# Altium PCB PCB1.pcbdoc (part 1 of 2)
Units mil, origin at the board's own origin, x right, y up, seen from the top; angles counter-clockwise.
Board outline 3879.65 x 2893.58 mil, 4 copper layers (Top Layer, Inner1, Inner2, Bottom Layer); 142 components, 140 nets, 675 pads, 157 vias.
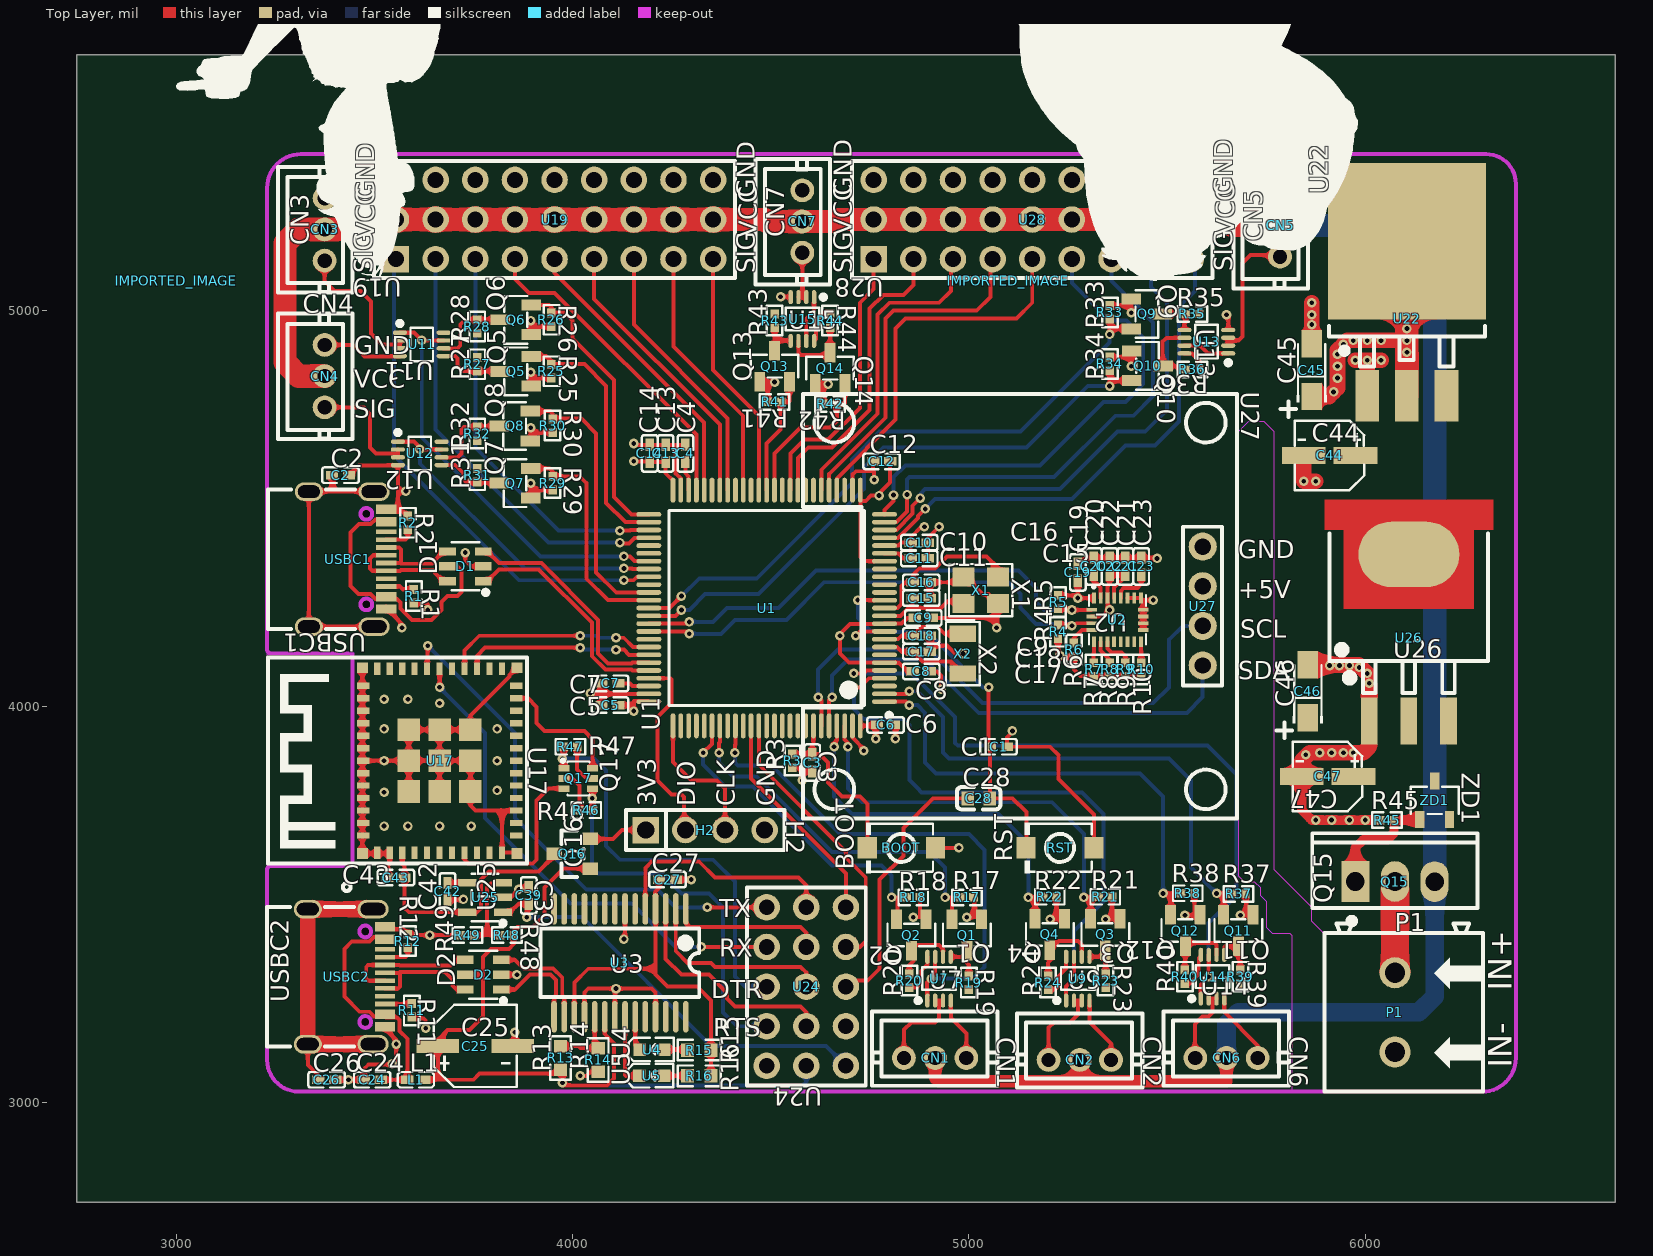
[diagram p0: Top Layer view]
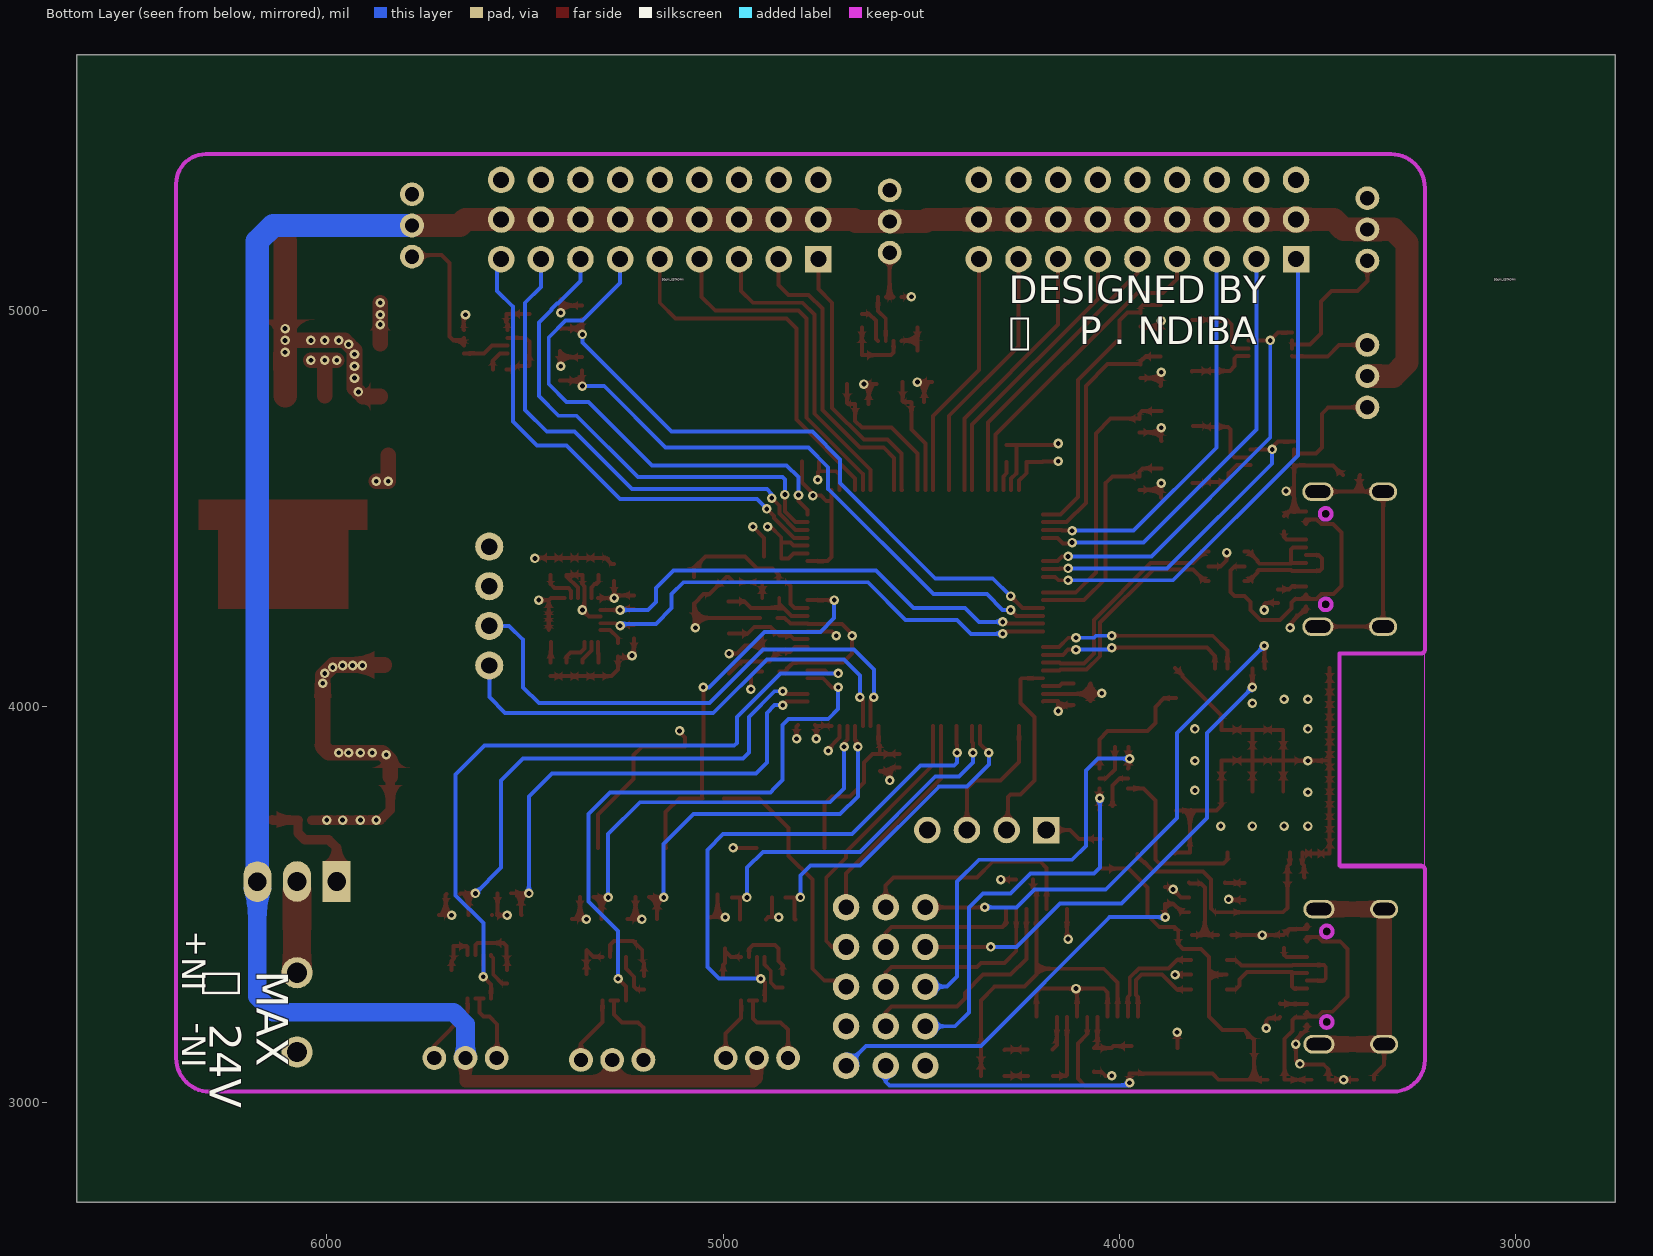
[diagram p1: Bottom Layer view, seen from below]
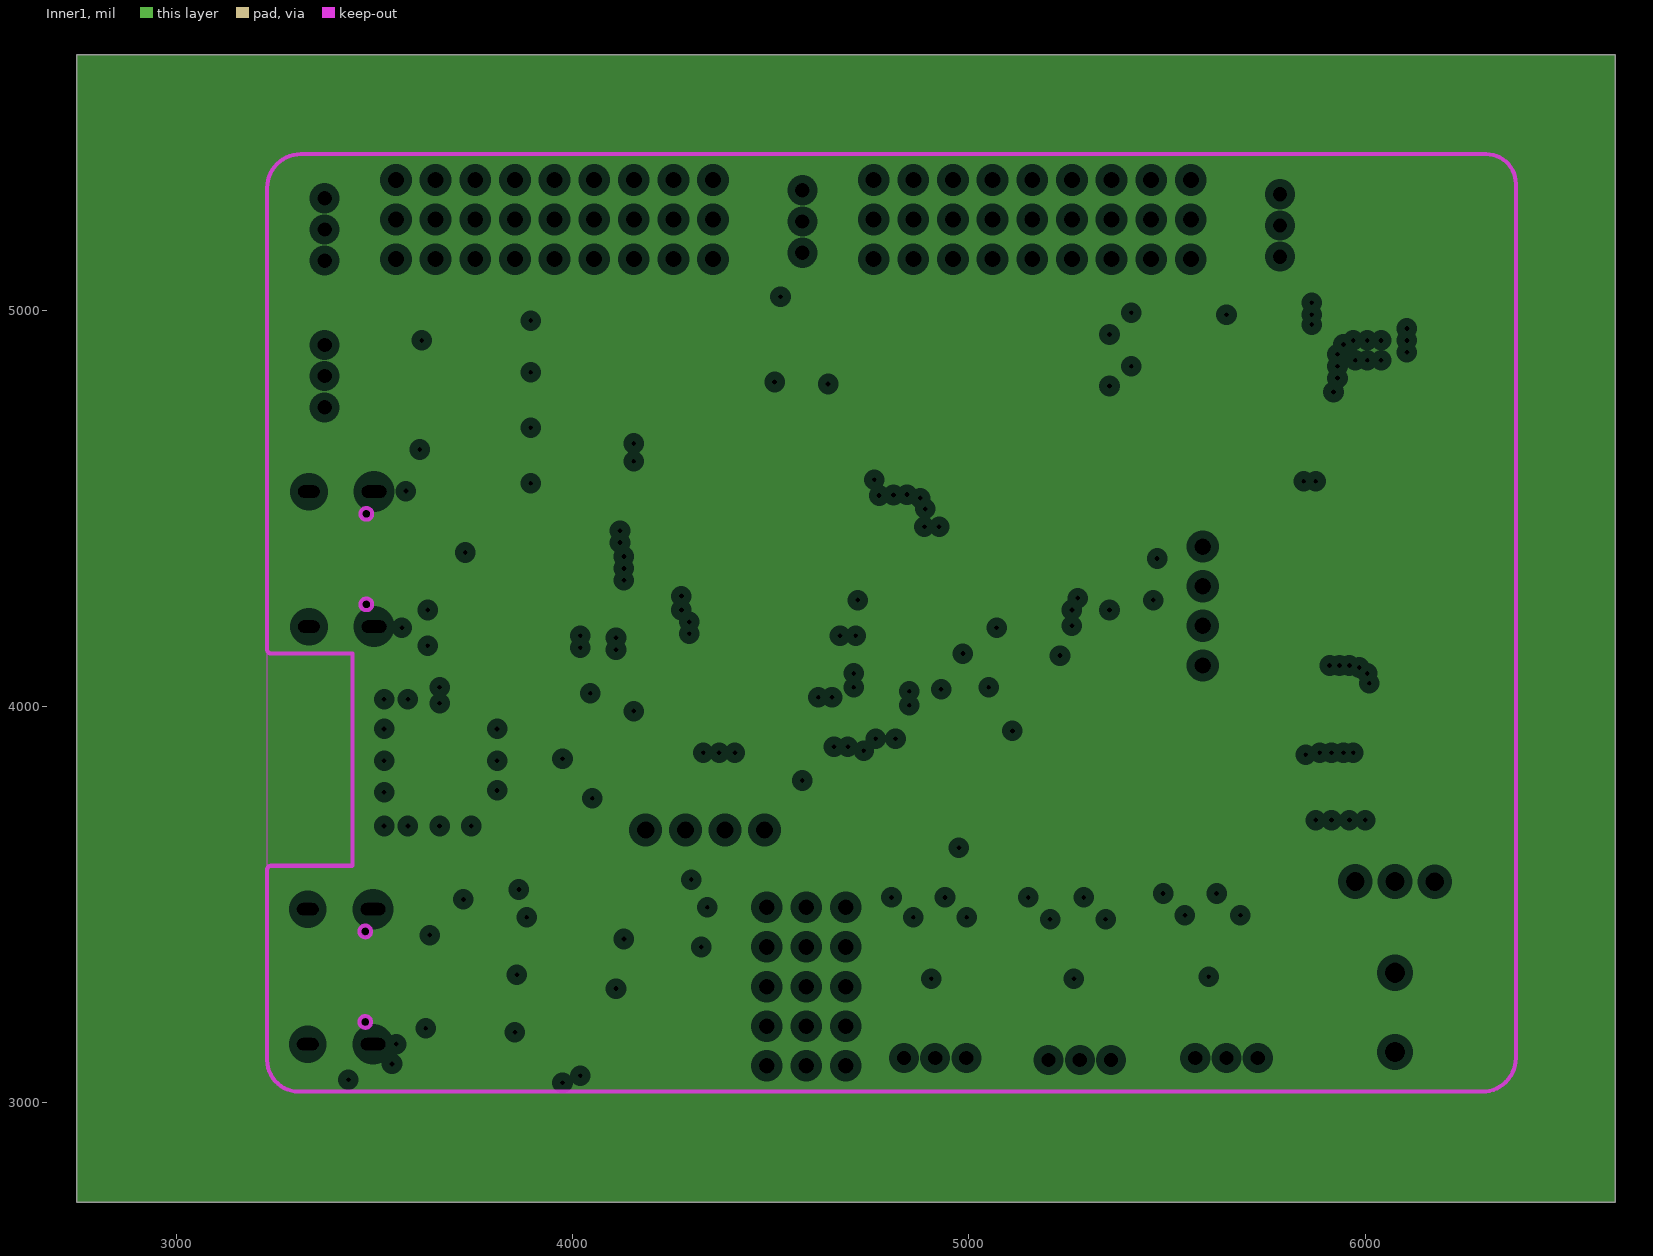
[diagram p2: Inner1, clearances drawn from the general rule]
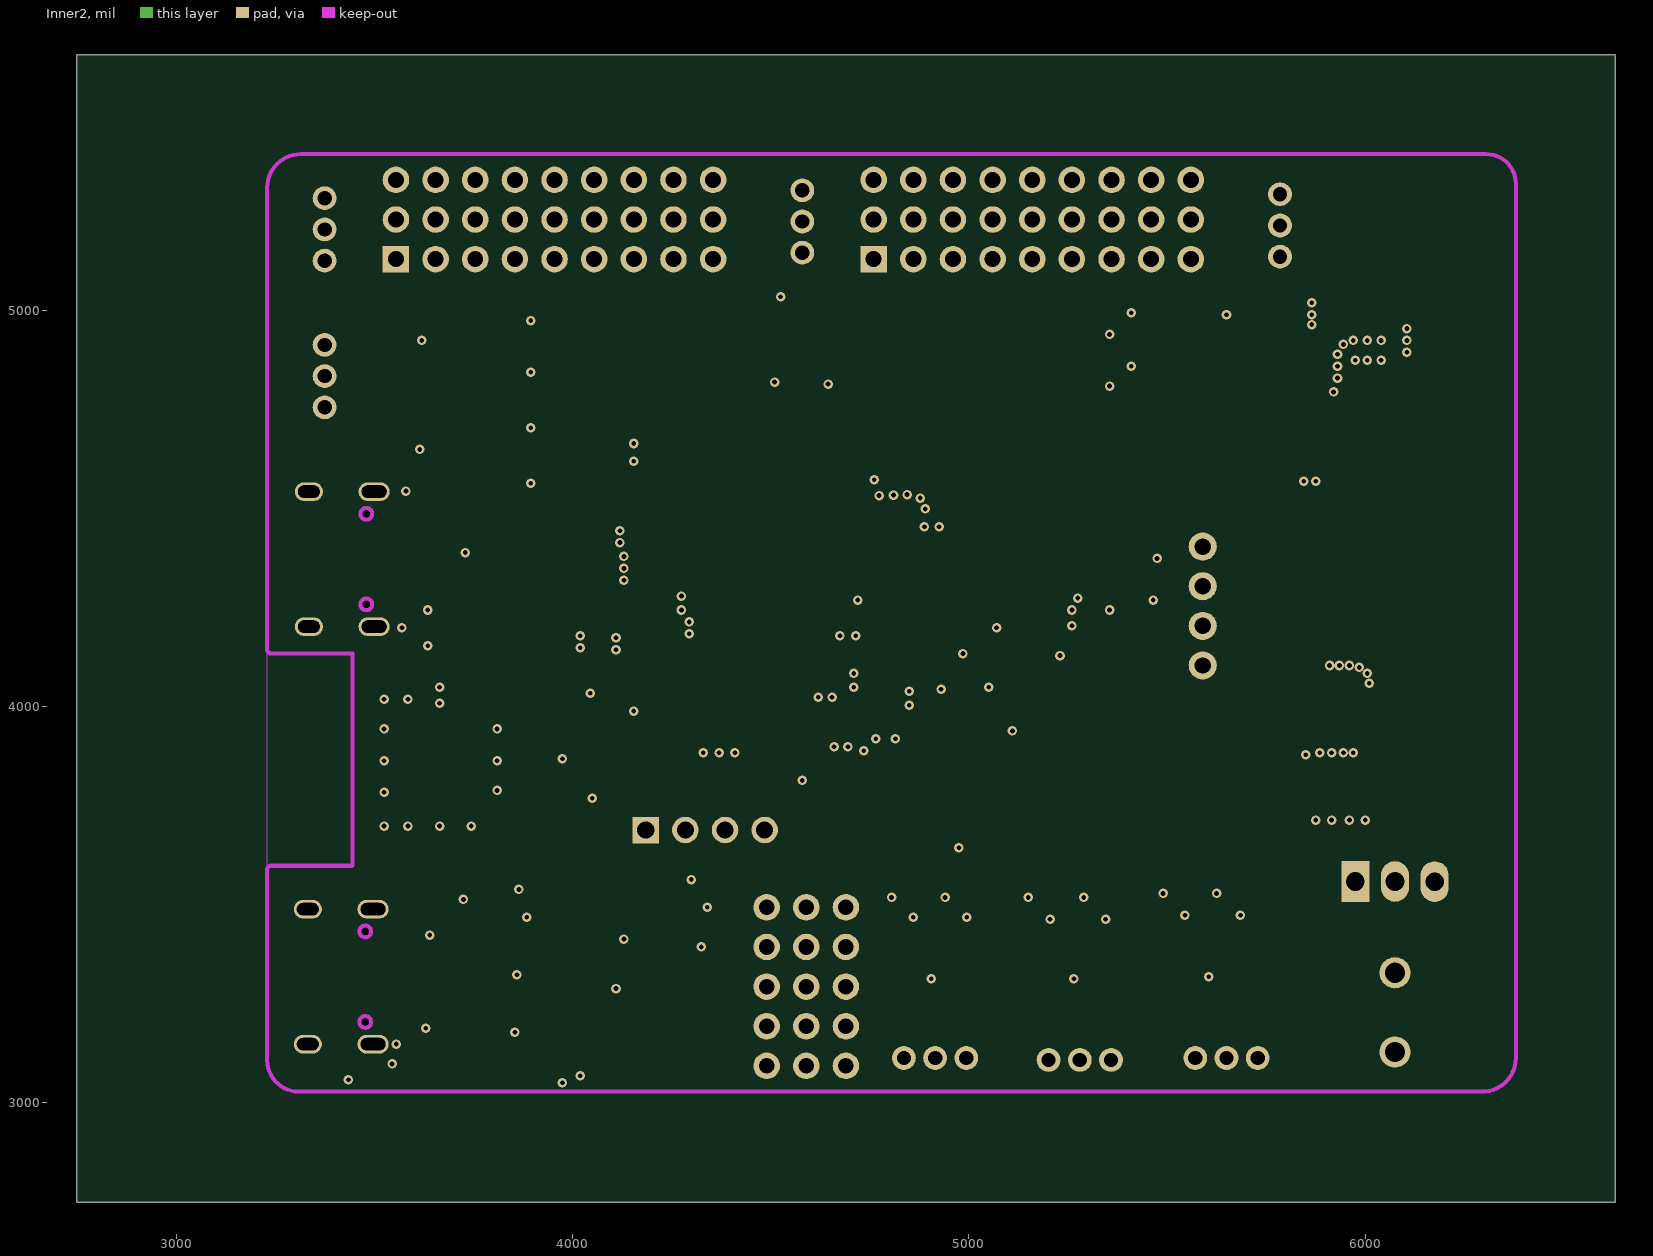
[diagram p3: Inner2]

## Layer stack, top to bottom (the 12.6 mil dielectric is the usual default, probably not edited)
Top Layer: signal copper (thickness not stored)
Dielectric: dielectric 12.6, FR-4, Dk 4.8
Inner1: plane copper (thickness not stored)
Dielectric: dielectric 12.6, FR-4, Dk 4.8
Inner2: signal copper (thickness not stored)
Dielectric: dielectric 12.6, FR-4, Dk 4.8
Bottom Layer: signal copper (thickness not stored)

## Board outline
6629.65,2750 2750,2750 2750,5643.58 6629.65,5643.58

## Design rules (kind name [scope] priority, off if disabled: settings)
BoardOutlineClearance copperThickness1oz [All] p0: genericclearance=10 ignorepadtopadclearanceinfootprint=FALSE except(0: Arc-SplitContinuation Track-SplitContinuation SMDPad-SplitContinuation THPad-SplitContinuation Via-SplitContinuation Fill-SplitContinuation Poly-SplitContinuation Region-SplitContinuation Text-SplitContinuation; 6: Track-CutoutEdge SMDPad-CutoutEdge THPad-CutoutEdge Via-CutoutEdge Region-CutoutEdge; 11.8: Track-OutlineEdge SMDPad-OutlineEdge THPad-OutlineEdge Via-OutlineEdge Fill-OutlineEdge Region-OutlineEdge Poly-OutlineEdge Text-OutlineEdge Fill-CutoutEdge)
BoardOutlineClearance copperThickness2oz [All] p0: genericclearance=10 ignorepadtopadclearanceinfootprint=FALSE except(0: Arc-SplitContinuation Track-SplitContinuation SMDPad-SplitContinuation THPad-SplitContinuation Via-SplitContinuation Fill-SplitContinuation Poly-SplitContinuation Region-SplitContinuation Text-SplitContinuation; 6: Track-CutoutEdge SMDPad-CutoutEdge THPad-CutoutEdge Via-CutoutEdge Region-CutoutEdge; 11.8: Track-OutlineEdge SMDPad-OutlineEdge THPad-OutlineEdge Via-OutlineEdge Fill-OutlineEdge Region-OutlineEdge Poly-OutlineEdge Text-OutlineEdge Fill-CutoutEdge)
Clearance copperThickness1oz [(InNet('OSC32_IN') OR InNet('GND') OR InNet('OSC32_OUT') OR InNet('$2N1585') OR InNet('+3V3') OR InNet('$2N1590') OR InNet('+5V') OR InNet('OSC_OUT') OR InNet('OSC_IN') OR InNet('$2N1592') OR InNet('$2N1593') OR InNet('$2N1595') OR InNet('$2N1605') OR InNet('$2N1601') OR InNet('SCL') OR InNet('SDA') OR InNet('$6N672') OR InNet('VCC') OR InNet('$6N490') OR InNet('SCL_2') OR InNet('SDA_2') OR InNet('NRST') OR InNet('AGND') OR InNet('VCCIO') OR InNet('$1N20642') OR InNet('$1N20641') OR InNet('BOOT') OR InNet('5V_FTDI') OR InNet('5V_FTDI_FIL') OR InNet('$4N17959') OR InNet('$4N20345') OR InNet('$4N20830') OR InNet('$4N21315') OR InNet('$4N21800') OR InNet('$4N22285') OR InNet('$4N22770') OR InNet('USBDP_UP') OR InNet('USBDM_UP') OR InNet('C_DN') OR InNet('5V_HOST') OR InNet('C_DP') OR InNet('USB_DP') OR InNet('USB_DN') OR InNet('FTDI_DN') OR InNet('FTDI_DP') OR InNet('SWDIO') OR InNet('SWCLK') OR InNet('UART4_TX') OR InNet('UART4_RX') OR InNet('UART7_TX') OR InNet('UART7_TXS') OR InNet('UART7_RX') OR InNet('UART7_RXS') OR InNet('UART9_TX') OR InNet('UART9_TXS') OR InNet('UART9_RX') OR InNet('UART9_RXS') OR InNet('UART5_TX') OR InNet('UART5_TXS') OR InNet('UART5_RX') OR InNet('UART5_RXS') OR InNet('UART8_TX') OR InNet('UART8_TXS') OR InNet('UART8_RX') OR InNet('UART8_RXS') OR InNet('UART10_TX') OR InNet('UART10_TXS') OR InNet('UART10_RX') OR InNet('UART10_RXS') OR InNet('UART6_TX') OR InNet('UART6_TXS') OR InNet('UART6_RX') OR InNet('UART6_RXS') OR InNet('$3N2642') OR InNet('$3N2650') OR InNet('$1N21099') OR InNet('$1N21098') OR InNet('$3N2651') OR InNet('$3N3207') OR InNet('$3N3206') OR InNet('DUP4') OR InNet('PB3') OR InNet('$1N20674') OR InNet('$1N20676') OR InNet('$1N20678') OR InNet('UART1_RX') OR InNet('UART1_TX') OR InNet('PD13') OR InNet('PD12') OR InNet('UART3_RX') OR InNet('UART3_TX') OR InNet('PB15') OR InNet('PB14') OR InNet('PB11') OR InNet('PB10') OR InNet('PE14') OR InNet('PE13') OR InNet('PE12') OR InNet('PE11') OR InNet('PE10') OR InNet('PE9') OR InNet('PB1') OR InNet('PB0') OR InNet('PA7') OR InNet('PA6') OR InNet('PA5') OR InNet('PA3') OR InNet('PA2') OR InNet('PA1') OR InNet('PA0') OR InNet('TX1') OR InNet('RX1') OR InNet('$3N2648') OR InNet('$3N2649') OR InNet('DUP7') OR InNet('DUP9') OR InNet('DUP5') OR InNet('DUP8') OR InNet('DUP10') OR InNet('DUP6') OR InNet('UART2_RX') OR InNet('UART2_TX') OR InNet('DTR') OR InNet('RTS') OR InNet('ESP_TX') OR InNet('ESP_RX') OR InNet('I00') OR InNet('EN') OR InNet('3V3_ESP') OR InNet('+5V_USB_FIL') OR InNet('$3N5399') OR InNet('$3N4810') OR InNet('RTS1') OR InNet('$3N4808') OR InNet('DTR1') OR InNet('VBUS_DET') OR InNet('$3N5472') OR InNet('UART4_TXS') OR InNet('UART4_RXS') OR InNet('AGND1'))] p1: gap=7 ignorepadtopadclearanceinfootprint=FALSE except(4: Track-Track; 6: Track-SMDPad SMDPad-SMDPad Track-THPad SMDPad-THPad THPad-THPad Track-Via SMDPad-Via THPad-Via Via-Via SMDPad-Fill THPad-Fill Via-Fill Fill-Fill Track-Region SMDPad-Region THPad-Region Via-Region Region-Region Track-Poly SMDPad-Poly THPad-Poly Via-Poly Fill-Poly Region-Poly Poly-Poly Track-Text SMDPad-Text THPad-Text Via-Text Fill-Text Region-Text Poly-Text Text-Text; 6.9: Track-Hole SMDPad-Hole THPad-Hole Via-Hole Fill-Hole Region-Hole Poly-Hole Text-Hole Sheet-Hole; 11.8: Track-Fill Fill-Region Track-Sheet SMDPad-Sheet THPad-Sheet Via-Sheet Fill-Sheet Region-Sheet Poly-Sheet Text-Sheet)
Clearance copperThickness2oz [All] p1: gap=7 ignorepadtopadclearanceinfootprint=FALSE except(6: Track-SMDPad SMDPad-SMDPad Track-THPad SMDPad-THPad THPad-THPad Track-Via SMDPad-Via THPad-Via Via-Via SMDPad-Fill THPad-Fill Via-Fill Fill-Fill Track-Region SMDPad-Region THPad-Region Via-Region Region-Region Track-Poly SMDPad-Poly THPad-Poly Via-Poly Fill-Poly Region-Poly Poly-Poly Track-Text SMDPad-Text THPad-Text Via-Text Fill-Text Region-Text Poly-Text Text-Text; 6.9: Track-Hole SMDPad-Hole THPad-Hole Via-Hole Fill-Hole Region-Hole Poly-Hole Text-Hole Sheet-Hole; 8: Track-Track; 11.8: Track-Fill Fill-Region Track-Sheet SMDPad-Sheet THPad-Sheet Via-Sheet Fill-Sheet Region-Sheet Poly-Sheet Text-Sheet)
DiffPairsRouting differentialPair [All] p1: maxuncoupledlength=10 minlimit=6 maxlimit=6 mostfreqgap=6 toplayer_minwidth=5 toplayer_prefwidth=10 toplayer_maxwidth=100 bottomlayer_minwidth=5 bottomlayer_prefwidth=10 bottomlayer_maxwidth=100 midlayer2_minwidth=5 midlayer2_prefwidth=10 midlayer2_maxwidth=100
PasteMaskExpansion pasteMaskExpansion [All] p1: expansion=0
PlaneConnect innerPlane [All] p1: planeconnectstyle=Relief reliefexpansion=20 reliefentries=4 reliefconductorwidth=10 reliefairgap=10
PolygonConnect copperRegion [All] p1: connectstyle=Relief reliefentries=4 reliefconductorwidth=10 polygonreliefangle="90 Angle" airgapwidth=10
RoutingVias viaSize [All] p1: viastyle="Through Hole" holewidth=12.0078 minholewidth=11.811 maxholewidth=248.0314 width=24.0158 minwidth=19.685 maxwidth=393.7008
SolderMaskExpansion solderMaskExpansion [All] p1: useseparateexpansions=TRUE expansion=2 expansionbottom=2
Width copperThickness1oz [All] p1: maxlimit=100 minlimit=5 preferedwidth=10
Width copperThickness2oz [All] p1: maxlimit=100 minlimit=8 preferedwidth=10

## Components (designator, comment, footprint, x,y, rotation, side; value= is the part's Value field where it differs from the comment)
BOOT "TS-1088-AR02016" SW-SMD_L3.9-W3.0-P4.45 4829.65,3643.58 r180 top
C1 "CT41G-0402-2X1-16V-0.1μF-K(N)" C0402 5074.65,3898.58 r180 top
C2 "CC0402KRX7R9BB472" C0402 3414.65,4583.58 r0 top
C3 "CT41G-0402-2X1-16V-0.1μF-K(N)" C0402 4604.65,3858.58 r90 top
C4 "GRM155R61A225KE95D" C0402 4284.65,4638.58 r270 top
C5 "GRM155R71A104KA01D" C0402 4094.65,4003.58 r180 top
C6 "GRM155R71A104KA01D" C0402 4789.65,3953.58 r0 top
C7 "GRM155R61A225KE95D" C0402 4094.65,4058.58 r180 top
C8 "GRM155R71A104KA01D" C0402 4879.65,4088.58 r0 top
C9 "GRM155R71A104KA01D" C0402 4884.65,4223.58 r0 top
C10 "GRM155R71A104KA01D" C0402 4874.65,4413.58 r0 top
C11 "GRM155R71A104KA01D" C0402 4874.65,4373.58 r0 top
C12 "GRM155R71A104KA01D" C0402 4779.65,4618.58 r0 top
C13 "GRM155R71A104KA01D" C0402 4234.65,4638.58 r90 top
C14 "CL05A475KP5NRNC" C0402 4194.65,4638.58 r90 top
C15 "TCC0402COG250K500AT" C0402 4879.65,4273.58 r180 top
C16 "TCC0402COG250K500AT" C0402 4879.65,4313.58 r180 top
C17 "TCC0402COG250K500AT" C0402 4879.65,4138.58 r180 top
C18 "TCC0402COG250K500AT" C0402 4879.65,4178.58 r180 top
C19 "CC0402KRX7R7BB104" C0402 5274.65,4338.58 r90 top
C20 "CC0402KRX7R7BB104" C0402 5314.65,4353.58 r270 top
C21 "CC0402KRX7R7BB104" C0402 5394.65,4353.58 r270 top
C22 "CL05A106MQ5NUNC" C0402 5354.65,4353.58 r270 top
C23 "CC0402KRX7R9BB103" C0402 5434.65,4353.58 r90 top
C24 "CL05A225MQ5NSNC" C0402 3494.65,3058.58 r0 top
C25 "RVT1C101M0505" CAP-SMD_BD5.0-L5.3-W5.3-LS6.3-FD 3754.65,3143.58 r0 top
C26 "CC0402KRX7R9BB472" C0402 3379.65,3058.58 r0 top
C27 "CC0402KRX7R7BB104" C0402 4239.65,3563.58 r180 top
C28 "CC0603KRX7R9BB104" C0603 5024.65,3768.58 r0 top
C39 "CL05A225MQ5NSNC" C0402 3889.65,3523.58 r90 top
C42 "CC0402KRX7R7BB104" C0402 3684.65,3533.58 r90 top
C43 "CL05A225MQ5NSNC" C0402 3554.65,3568.58 r0 top
C44 "RST10UF16V013" CAP-SMD_BD4.0-L4.3-W4.3-FD 5909.65,4633.58 r180 top
C45 "TAJA106K016RNJ" CAP-SMD_L3.2-W1.6-RD-C7171 5864.65,4848.58 r90 top
C46 "TAJA106K016RNJ" CAP-SMD_L3.2-W1.6-RD-C7171 5854.65,4038.58 r90 top
C47 "RST10UF16V013" CAP-SMD_BD4.0-L4.3-W4.3-FD 5904.65,3823.58 r180 top
CN1 "WAFER-PH2.0-3PZZ" CONN-TH_PH2.0D-L-3P 4914.65,3113.58 r0 top
CN2 "WAFER-PH2.0-3PZZ" CONN-TH_PH2.0D-L-3P 5279.65,3108.58 r0 top
CN3 "WAFER-PH2.0-3PZZ" CONN-TH_PH2.0D-L-3P 3374.65,5203.58 r90 top
CN4 "WAFER-PH2.0-3PZZ" CONN-TH_PH2.0D-L-3P 3374.65,4833.58 r90 top
CN5 "WAFER-PH2.0-3PZZ" CONN-TH_PH2.0D-L-3P 5784.65,5213.58 r90 top
CN6 "WAFER-PH2.0-3PZZ" CONN-TH_PH2.0D-L-3P 5649.65,3113.58 r0 top
CN7 "WAFER-PH2.0-3PZZ" CONN-TH_PH2.0D-L-3P 4579.65,5223.58 r90 top
D1 "USBLC6-2SC6_C2827654" SOT-23-6_L2.9-W1.6-P0.95-LS2.8-BL 3729.65,4353.58 r90 top
D2 "USBLC6-2SC6_C2827654" SOT-23-6_L2.9-W1.6-P0.95-LS2.8-BL 3774.65,3323.58 r90 top
H2 "PZ254V-11-04P" HDR-TH_4P-P2.54-V-M 4334.65,3688.58 r0 top
IMPORTED_IMAGE "IMPORTED_IMAGE" IMPORTED_IMAGE 5099.08,5073.58 r0 top
IMPORTED_IMAGE "IMPORTED_IMAGE" IMPORTED_IMAGE 3000,5073.58 r0 top
L1 "BLM15PX121SN1D" L0402 3604.65,3058.58 r0 top
P1 "WJ500V-5.08-2P" CONN-TH_2P-P5.00_WJ500V-5.08-2P 6074.65,3228.58 r270 top
Q1 "BSS138_C5224260" SOT-23-3_L2.9-W1.3-P1.90-LS2.4-BR 4994.65,3423.58 r90 top
Q2 "BSS138_C5224260" SOT-23-3_L2.9-W1.3-P1.90-LS2.4-BR 4854.65,3423.58 r90 top
Q3 "BSS138_C5224260" SOT-23-3_L2.9-W1.3-P1.90-LS2.4-BR 5343.81,3425.2 r90 top
Q4 "BSS138_C5224260" SOT-23-3_L2.9-W1.3-P1.90-LS2.4-BR 5203.81,3425.2 r90 top
Q5 "BSS138_C5224260" SOT-23-3_L2.9-W1.3-P1.90-LS2.4-BR 3856.78,4845.71 r0 top
Q6 "BSS138_C5224260" SOT-23-3_L2.9-W1.3-P1.90-LS2.4-BR 3856.78,4975.71 r0 top
Q7 "BSS138_C5224260" SOT-23-3_L2.9-W1.3-P1.90-LS2.4-BR 3854.65,4563.58 r0 top
Q8 "BSS138_C5224260" SOT-23-3_L2.9-W1.3-P1.90-LS2.4-BR 3854.08,4707.73 r0 top
Q9 "BSS138_C5224260" SOT-23-3_L2.9-W1.3-P1.90-LS2.4-BR 5448.78,4990.34 r180 top
Q10 "BSS138_C5224260" SOT-23-3_L2.9-W1.3-P1.90-LS2.4-BR 5450.44,4859.45 r180 top
Q11 "BSS138_C5224260" SOT-23-3_L2.9-W1.3-P1.90-LS2.4-BR 5679.38,3434.95 r90 top
Q12 "BSS138_C5224260" SOT-23-3_L2.9-W1.3-P1.90-LS2.4-BR 5545.9,3434.95 r90 top
Q13 "BSS138_C5224260" SOT-23-3_L2.9-W1.3-P1.90-LS2.4-BR 4509.65,4858.58 r270 top
Q14 "BSS138_C5224260" SOT-23-3_L2.9-W1.3-P1.90-LS2.4-BR 4649.65,4853.58 r270 top
Q15 "IRF9540NPBF" TO-220-3_L10.0-W4.5-P2.54-L 6074.65,3558.58 r0 top
Q16 "IRLML6402TR(UMW)" SOT-23_L2.9-W1.3-P1.90-LS2.4-BR 3999.65,3628.58 r0 top
Q17 "BC847BDW1T1G" SOT-363_L2.0-W1.3-P0.65-LS2.1-TL 4014.65,3818.58 r0 top
R1 "RMC04025.1K1%N" R0402 3599.65,4278.58 r90 top
R2 "RMC04025.1K1%N" R0402 3584.65,4463.58 r90 top
R3 "RC0402FR-0710KL" R0402 4554.65,3863.58 r90 top
R4 "RC0402FR-0710KL" R0402 5224.65,4188.58 r270 top
R5 "RC0402FR-0710KL" R0402 5224.65,4263.58 r90 top
R6 "RC0402FR-0710KL" R0402 5264.65,4143.58 r270 top
R7 "RC0402FR-0710KL" R0402 5314.65,4093.58 r270 top
R8 "RC0402FR-0710KL" R0402 5354.65,4093.58 r90 top
R9 "RC0402FR-0710KL" R0402 5394.65,4093.58 r90 top
R10 "RC0402FR-0710KL" R0402 5434.65,4093.58 r270 top
R11 "RMC04025.1K1%N" R0402 3594.65,3233.58 r90 top
R12 "RMC04025.1K1%N" R0402 3584.65,3408.58 r90 top
R13 "RC0603JR-074K7L" R0603 3969.65,3113.58 r270 top
R14 "FRC0603J103TS" R0603 4064.65,3108.58 r270 top
R15 "RT0603BRE07250RL" R0603 4319.65,3133.58 r0 top
R16 "RT0603BRE07250RL" R0603 4319.65,3068.58 r0 top
R17 "RC0402FR-0710KL" R0402 4994.65,3518.58 r0 top
R18 "RC0402FR-0710KL" R0402 4859.65,3518.58 r0 top
R19 "RC0402FR-0710KL" R0402 4999.65,3303.58 r270 top
R20 "RC0402FR-0710KL" R0402 4849.65,3308.58 r270 top
R21 "RC0402FR-0710KL" R0402 5343.81,3520.2 r0 top
R22 "RC0402FR-0710KL" R0402 5203.81,3520.2 r0 top
R23 "RC0402FR-0710KL" R0402 5344.65,3308.58 r270 top
R24 "RC0402FR-0710KL" R0402 5199.65,3303.58 r270 top
R25 "RC0402FR-0710KL" R0402 3946.78,4845.71 r270 top
R26 "RC0402FR-0710KL" R0402 3946.78,4975.71 r270 top
R27 "RC0402FR-0710KL" R0402 3759.65,4863.58 r90 top
R28 "RC0402FR-0710KL" R0402 3759.65,4958.58 r270 top
R29 "RC0402FR-0710KL" R0402 3949.65,4563.58 r270 top
R30 "RC0402FR-0710KL" R0402 3949.65,4708.58 r270 top
R31 "RC0402FR-0710KL" R0402 3759.65,4583.58 r90 top
R32 "RC0402FR-0710KL" R0402 3759.65,4688.58 r270 top
R33 "RC0402FR-0710KL" R0402 5355.44,4994.45 r90 top
R34 "RC0402FR-0710KL" R0402 5355.44,4864.45 r90 top
R35 "RC0402FR-0710KL" R0402 5563.78,4990.34 r0 top
R36 "RC0402FR-0710KL" R0402 5563.78,4850.34 r0 top
R37 "RC0402FR-0710KL" R0402 5680.05,3527.4 r0 top
R38 "RC0402FR-0710KL" R0402 5551.82,3529.08 r0 top
R39 "RC0402FR-0710KL" R0402 5684.65,3318.58 r270 top
R40 "RC0402FR-0710KL" R0402 5544.65,3318.58 r270 top
R41 "RC0402FR-0710KL" R0402 4509.65,4768.58 r180 top
R42 "RC0402FR-0710KL" R0402 4649.65,4763.58 r180 top
R43 "RC0402FR-0710KL" R0402 4509.65,4973.58 r90 top
R44 "RC0402FR-0710KL" R0402 4649.65,4973.58 r90 top
R45 "RC0402FR-0710KL" R0402 6054.65,3713.58 r0 top
R46 "RC0402FR-0710KL" R0402 4034.65,3738.58 r0 top
R47 "RC0402FR-0710KL" R0402 3994.65,3898.58 r0 top
R48 "RC0402FR-07100KL" R0402 3834.65,3423.58 r0 top
R49 "RC0402FR-07100KL" R0402 3734.65,3423.58 r0 top
RST "TS-1088-AR02016" SW-SMD_L3.9-W3.0-P4.45 5229.65,3643.58 r180 top
U1 "STM32H723VGT6" LQFP-100_L14.0-W14.0-P0.50-LS16.0-BL 4489.65,4248.58 r90 top
U2 "LSM9DS1TR" LGA-24_L3.5-W3.0-P0.43-TL 5374.65,4218.58 r0 top
U3 "FT232RL-REEL" SSOP-28_L10.2-W5.3-P0.65-LS7.8-BL 4119.65,3353.58 r180 top
U4 "NCD0603C4" LED0603-RD 4200.53,3134.86 r0 top
U5 "NCD0603C4" LED0603-RD 4199.65,3068.58 r0 top
U7 "SN74LVC2G241DCUR" VSSOP-8_L2.3-W2.0-P0.50-LS3.1-BR 4924.65,3313.58 r270 top
U9 "SN74LVC2G241DCUR" VSSOP-8_L2.3-W2.0-P0.50-LS3.1-BR 5274.65,3313.58 r270 top
U11 "SN74LVC2G241DCUR" VSSOP-8_L2.3-W2.0-P0.50-LS3.1-BR 3619.65,4913.58 r180 top
U12 "SN74LVC2G241DCUR" VSSOP-8_L2.3-W2.0-P0.50-LS3.1-BR 3614.65,4638.58 r180 top
U13 "SN74LVC2G241DCUR" VSSOP-8_L2.3-W2.0-P0.50-LS3.1-BR 5598.78,4920.34 r0 top
U14 "SN74LVC2G241DCUR" VSSOP-8_L2.3-W2.0-P0.50-LS3.1-BR 5614.65,3318.58 r270 top
U15 "SN74LVC2G241DCUR" VSSOP-8_L2.3-W2.0-P0.50-LS3.1-BR 4579.75,4977.52 r90 top
U17 "ESP32-PICO-MINI-02-N8R2" BULETM-SMD_ESP32-PICO-MINI-02-N8R2 3664.65,3863.58 r90 top
U19 "KH-2.54PH180-3X9P-L11.5" HDR-TH_27P-P2.54-V-M-R3-C9-S5.08 3954.65,5228.58 r0 top
U22 "LM1085S-3.3/TR" TO-263-3_L8.6-W10.2-P2.54-LS14.4-BR 6104.65,4978.58 r270 top
U24 "HX PZ2.54-3x5P ZZ" HDR-TH_15P-P2.54-V-M-R3-C5-S7.5 4589.65,3293.58 r90 top
U25 "SPX3819M5-L-3-3/TR" SOT-23-5_L3.0-W1.7-P0.95-LS2.8-BL 3779.65,3518.58 r90 top
U26 "LM1084ISX-5.0/NOPB" TO-263-3_L10.2-W8.6-P2.54-LS14.4-TL 6109.65,4173.58 r90 top
U27 "HS96L03W2C03" OLED-TH_L27.8-W27.2-P2.54_C9900033791 5589.65,4253.58 r270 top
U28 "KH-2.54PH180-3X9P-L11.5" HDR-TH_27P-P2.54-V-M-R3-C9-S5.08 5159.65,5228.58 r0 top
USBC1 "TYPE-C-31-M-12" USB-C_SMD-TYPE-C-31-M-12 3432.39,4371.92 r270 top
USBC2 "TYPE-C-31-M-12" USB-C_SMD-TYPE-C-31-M-12 3429.65,3318.58 r270 top
X1 "X322525MOB4SI" CRYSTAL-SMD_4P-L3.2-W2.5-BL 5029.65,4293.58 r0 top
X2 "X321532768KGD2SI" OSC-SMD_L3.2-W1.5 4984.65,4133.58 r270 top
ZD1 "BZX84C33LT1G" SOT-23-3_L2.9-W1.6-P1.90-LS2.8-BR 6174.65,3763.58 r270 top

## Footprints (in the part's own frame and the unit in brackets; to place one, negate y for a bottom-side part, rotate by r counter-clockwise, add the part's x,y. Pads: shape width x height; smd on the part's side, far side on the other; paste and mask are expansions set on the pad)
BULETM-SMD_ESP32-PICO-MINI-02-N8R2 [mm]
  rect 0.8x0.4 smd: 1(-5.9,4) 2(-5.9,3.2) 3(-5.9,2.4) 4(-5.9,1.6) 5(-5.9,0.8) 6(-5.9,0) 7(-5.9,-0.8) 8(-5.9,-1.6) 9(-5.9,-2.4) 10(-5.9,-3.2) 11(-5.9,-4) 25(5.9,-4) 26(5.9,-3.2) 27(5.9,-2.4) 28(5.9,-1.6) 29(5.9,-0.8) 30(5.9,0) 31(5.9,0.8) 32(5.9,1.6) 33(5.9,2.4) 34(5.9,3.2) 35(5.9,4)
  rect 0.4x0.8 smd: 12(-4.8,-4.9) 13(-4,-4.9) 14(-3.2,-4.9) 15(-2.4,-4.9) 16(-1.6,-4.9) 17(-0.8,-4.9) 18(0,-4.9) 19(0.8,-4.9) 20(1.6,-4.9) 21(2.4,-4.9) 22(3.2,-4.9) 23(4,-4.9) 24(4.8,-4.9) 36(4.8,4.9) 37(4,4.9) 38(3.2,4.9) 39(2.4,4.9) 40(1.6,4.9) 41(0.8,4.9) 42(0,4.9) 43(-0.8,4.9) 44(-1.6,4.9) 45(-2.4,4.9) 46(-3.2,4.9) 47(-4,4.9) 48(-4.8,4.9)
  rect 1.45x1.45 smd: 49(-1.975,-1.975) 49(-1.975,0) 49(-1.975,1.975) 49(0,1.975) 49(0,0) 49(0,-1.975) 49(1.975,-1.975) 49(1.975,0) 49(1.975,1.975)
  rect 0.7x0.7 smd: 50(5.95,4.95) 51(5.95,-4.95) 52(-5.95,-4.95) 53(-5.95,4.95)
  silkscreen extent -8.35,-5.6 6.6,11
C0402 [mm]
  rect 0.79x0.54 smd: 1(-0.545,0) 2(0.545,0)
  silkscreen extent -1.17,-0.5 1.17,0.5
C0603 [mm]
  rect 0.8x0.9 smd: 1(-0.7,0) 2(0.7,0)
  silkscreen extent -1.41,-0.71 1.39,0.72
CAP-SMD_BD4.0-L4.3-W4.3-FD [mm]
  rect 2.8x1.1 smd: 1(-1.661,0) 2(1.661,0)
  silkscreen extent -2.22,-2.23 2.24,2.23
CAP-SMD_BD5.0-L5.3-W5.3-LS6.3-FD [mm]
  rect 2.7x0.91 smd: 1(-2.4,0) 2(2.4,0)
  silkscreen extent -2.66,-2.62 2.66,2.65
CAP-SMD_L3.2-W1.6-RD-C7171 [mil]
  rect 69.19x51.02 smd: 1(-66.39,0) 2(66.39,0)
  silkscreen extent -118,-37 66,79
CONN-TH_2P-P5.00_WJ500V-5.08-2P [mm]
  round 2 hole 1.3: 1(-2.54,0) 2(2.54,0)
  silkscreen extent -5.68,-4.52 5.08,5.64
CONN-TH_PH2.0D-L-3P [mil]
  round 60 hole 36: 1(-78.74,0) 2(0,0) 3(78.74,0)
  silkscreen extent -159,-70 158,118
CRYSTAL-SMD_4P-L3.2-W2.5-BL [mm]
  rect 1.4x1.2 smd: 1(-1.1,-0.85) 2(1.1,-0.85) 3(1.1,0.85) 4(-1.1,0.85)
  silkscreen extent -2.26,-1.91 2.03,1.68
HDR-TH_4P-P2.54-V-M [mm]
  rect 1.7x1.7 hole 1.1: 1(-3.81,0)
  round 1.7 hole 1.1: 2(-1.27,0) 3(1.27,0) 4(3.81,0)
  silkscreen extent -5.08,-1.27 5.08,1.27
HDR-TH_15P-P2.54-V-M-R3-C5-S7.5 [mm]
  round 1.7 hole 1: 1(-5.08,-2.54) 2(-5.08,0) 3(-5.08,2.54) 4(-2.54,-2.54) 5(-2.54,0) 6(-2.54,2.54) 7(0,-2.54) 8(0,0) 9(0,2.54) 10(2.54,-2.54) 11(2.54,0) 12(2.54,2.54) 13(5.08,-2.54) 14(5.08,0) 15(5.08,2.54)
  silkscreen extent -6.35,-3.81 6.35,3.81
HDR-TH_27P-P2.54-V-M-R3-C9-S5.08 [mm]
  rect 1.7x1.7 hole 1.02: 1(-10.16,-2.54)
  round 1.7 hole 1.02: 2(-10.16,0) 3(-10.16,2.54) 4(-7.62,-2.54) 5(-7.62,0) 6(-7.62,2.54) 7(-5.08,-2.54) 8(-5.08,0) 9(-5.08,2.54) 10(-2.54,-2.54) 11(-2.54,0) 12(-2.54,2.54) 13(0,-2.54) 14(0,0) 15(0,2.54) 16(2.54,-2.54) 17(2.54,0) 18(2.54,2.54) 19(5.08,-2.54) 20(5.08,0) 21(5.08,2.54) 22(7.62,-2.54) 23(7.62,0) 24(7.62,2.54) 25(10.16,-2.54) 26(10.16,0) 27(10.16,2.54)
  silkscreen extent -11.56,-3.75 11.56,3.75
IMPORTED_IMAGE [mil]
  silkscreen extent 0,0 881,1339
L0402 [mm]
  rect 0.79x0.54 smd: 1(-0.545,0) 2(0.545,0)
  silkscreen extent -1.17,-0.5 1.17,0.5
LED0603-RD [mm]
  rect 0.8x0.8 smd: 1(-0.799,0) 2(0.799,0)
  silkscreen extent -1.49,-0.75 1.39,0.76
LGA-24_L3.5-W3.0-P0.43-TL [mm]
  rect 0.241x0.7 smd: 1(-1.505,1.4) 6(-1.505,-1.4) 7(-1.075,-1.4) 8(-0.645,-1.4) 9(-0.215,-1.4) 10(0.215,-1.4) 11(0.645,-1.4) 12(1.075,-1.4) 13(1.505,-1.4) 18(1.505,1.4) 19(1.075,1.4) 20(0.645,1.4) 21(0.215,1.4) 22(-0.215,1.4) 23(-0.645,1.4) 24(-1.075,1.4)
  rect 0.7x0.241 smd: 2(-1.65,0.645) 3(-1.65,0.215) 4(-1.65,-0.215) 5(-1.65,-0.645) 14(1.65,-0.645) 15(1.65,-0.215) 16(1.65,0.215) 17(1.65,0.645)
  silkscreen extent -1.83,-1.58 1.83,2.22
LQFP-100_L14.0-W14.0-P0.50-LS16.0-BL [mm]
  oval 0.3x1.6 smd: 1(-6,-7.55) 2(-5.5,-7.55) 3(-5,-7.55) 4(-4.5,-7.55) 5(-4,-7.55) 6(-3.5,-7.55) 7(-3,-7.55) 8(-2.5,-7.55) 9(-2,-7.55) 10(-1.5,-7.55) 11(-1,-7.55) 12(-0.5,-7.55) 13(0,-7.55) 14(0.5,-7.55) 15(1,-7.55) 16(1.5,-7.55) 17(2,-7.55) 18(2.5,-7.55) 19(3,-7.55) 20(3.5,-7.55) 21(4,-7.55) 22(4.5,-7.55) 23(5,-7.55) 24(5.5,-7.55) 25(6,-7.55) 51(6,7.55) 52(5.5,7.55) 53(5,7.55) 54(4.5,7.55) 55(4,7.55) 56(3.5,7.55) 57(3,7.55) 58(2.5,7.55) 59(2,7.55) 60(1.5,7.55) 61(1,7.55) 62(0.5,7.55) 63(0,7.55) 64(-0.5,7.55) 65(-1,7.55) 66(-1.5,7.55) 67(-2,7.55) 68(-2.5,7.55) 69(-3,7.55) 70(-3.5,7.55) 71(-4,7.55) 72(-4.5,7.55) 73(-5,7.55) 74(-5.5,7.55) 75(-6,7.55)
  oval 1.6x0.3 smd: 26(7.55,-6) 27(7.55,-5.5) 28(7.55,-5) 29(7.55,-4.5) 30(7.55,-4) 31(7.55,-3.5) 32(7.55,-3) 33(7.55,-2.5) 34(7.55,-2) 35(7.55,-1.5) 36(7.55,-1) 37(7.55,-0.5) 38(7.55,0) 39(7.55,0.5) 40(7.55,1) 41(7.55,1.5) 42(7.55,2) 43(7.55,2.5) 44(7.55,3) 45(7.55,3.5) 46(7.55,4) 47(7.55,4.5) 48(7.55,5) 49(7.55,5.5) 50(7.55,6) 76(-7.55,6) 77(-7.55,5.5) 78(-7.55,5) 79(-7.55,4.5) 80(-7.55,4) 81(-7.55,3.5) 82(-7.55,3) 83(-7.55,2.5) 84(-7.55,2) 85(-7.55,1.5) 86(-7.55,1) 87(-7.55,0.5) 88(-7.55,0) 89(-7.55,-0.5) 90(-7.55,-1) 91(-7.55,-1.5) 92(-7.55,-2) 93(-7.55,-2.5) 94(-7.55,-3) 95(-7.55,-3.5) 96(-7.55,-4) 97(-7.55,-4.5) 98(-7.55,-5) 99(-7.55,-5.5) 100(-7.55,-6)
  silkscreen extent -7.03,-8 6.25,6.25
OLED-TH_L27.8-W27.2-P2.54_C9900033791 [mm]
  round 1.8 hole 1.05: 1(-3.81,0) 2(-1.27,0) 3(1.27,0) 4(3.81,0)
  silkscreen extent -13.6,-25.6 13.6,2.2
OSC-SMD_L3.2-W1.5 [mm]
  rect 1.05x1.7 smd: 1(-1.275,0) 2(1.275,0)
  silkscreen extent -2.03,-1.08 2.03,1.08
R0402 [mm]
  rect 0.566x0.54 smd: 1(-0.433,0) 2(0.433,0)
  silkscreen extent -0.94,-0.5 0.94,0.5
R0603 [mil]
  rect 31.75x34.02 smd: 1(-29.66,0) 2(29.66,0)
  silkscreen extent -55,-26 55,26
SOT-23-3_L2.9-W1.3-P1.90-LS2.4-BR [mm]
  rect 1.25x0.7 smd: 1(1,-0.95) 2(1,0.95) 3(-1,0)
  silkscreen extent -0.73,-1.53 0.73,1.53
SOT-23-3_L2.9-W1.6-P1.90-LS2.8-BR [mm]
  rect 1.07x0.6 smd: 1(1.235,-0.95) 2(1.235,0.95) 3(-1.235,0)
  silkscreen extent -0.88,-1.54 0.88,1.54
SOT-23-5_L3.0-W1.7-P0.95-LS2.8-BL [mm]
  rect 0.49x1.157 smd: 1(-0.95,-1.154) 2(0,-1.154) 3(0.95,-1.154)
  rect 0.49x1.175 smd: 4(0.95,1.154) 5(-0.95,1.154)
  silkscreen extent -1.8,-1.29 1.53,0.85
SOT-23-6_L2.9-W1.6-P0.95-LS2.8-BL [mil]
  rect 20.95x42.2 smd: 1(-37.4,-45.24) 2(0,-45.24) 3(37.4,-45.24) 4(37.4,45.24) 5(0,45.24) 6(-37.4,45.24)
  silkscreen extent -72,-57 61,35
SOT-23_L2.9-W1.3-P1.90-LS2.4-BR [mm]
  rect 1x0.8 smd: 1(1.15,-0.95) 2(1.15,0.95) 3(-1.15,0)
  silkscreen extent -0.7,-1.5 0.7,1.5
SOT-363_L2.0-W1.3-P0.65-LS2.1-TL [mm]
  rect 0.7x0.42 smd: 1(-0.92,0.65) 2(-0.92,0) 3(-0.92,-0.65) 4(0.92,-0.65) 5(0.92,0) 6(0.92,0.65)
  silkscreen extent -1.09,-1.1 0.7,1.24
SSOP-28_L10.2-W5.3-P0.65-LS7.8-BL [mil]
  oval 14.33x79.35 smd: 1(-166.34,-136.03) 2(-140.75,-136.03) 3(-115.16,-136.03) 4(-89.57,-136.03) 5(-63.98,-136.03) 6(-38.39,-136.03) 7(-12.79,-136.03) 8(12.8,-136.03) 9(38.39,-136.03) 10(63.98,-136.03) 11(89.57,-136.03) 12(115.16,-136.03) 13(140.75,-136.03) 14(166.34,-136.03) 15(166.34,136.03) 16(140.75,136.03) 17(115.16,136.03) 18(89.57,136.03) 19(63.98,136.03) 20(38.39,136.03) 21(12.8,136.03) 22(-12.79,136.03) 23(-38.39,136.03) 24(-63.98,136.03) 25(-89.57,136.03) 26(-115.16,136.03) 27(-140.75,136.03) 28(-166.34,136.03)
  silkscreen extent -200,-87 200,87
SW-SMD_L3.9-W3.0-P4.45 [mm]
  rect 1.23x1.36 smd: 1(-2.185,0) 2(2.185,0)
  silkscreen extent -2.03,-1.62 2.25,1.62
TO-220-3_L10.0-W4.5-P2.54-L [mm]
  rect 1.8x2.6 hole 1.2: 1(-2.54,0.005)
  oval 1.8x2.6 hole 1.2: 2(0,0.005)
  oval 1.8x2.6 hole 1.2 copper offset 0,0: 3(2.54,-0.005)
  silkscreen extent -5.3,-2.73 5.3,3.09
TO-263-3_L8.6-W10.2-P2.54-LS14.4-BR [mm]
  rect 3.3x1.511 smd: 1(4.952,-2.54) 2(4.952,0) 3(4.952,2.54)
  rect 10.02x10.122 smd: 4(-4.952,0)
  silkscreen extent 0.46,-5 3.06,5
TO-263-3_L10.2-W8.6-P2.54-LS14.4-TL [mm]
  rect 3x1.07 smd: 1(-5.338,2.54) 2(-5.338,0) 3(-5.338,-2.54)
  oval 4.194x6.48 smd: 4(5.338,0)
  Top Layer region: 1.842,-4.16 1.842,4.16 6.922,4.16 6.922,5.4 8.832,5.4 8.832,-5.4 6.922,-5.4 6.922,-4.16
  silkscreen extent -3.55,-5.08 6.69,5.08
USB-C_SMD-TYPE-C-31-M-12 [mm]
  oval 1.2x2 hole 0.8 slot 1.6 at 90 deg: 0(-4.325,1.706) 1(4.325,1.706)
  oval 1.2x1.8 hole 0.8 slot 1.4 at 90 deg: 2(4.325,-2.474) 3(-4.325,-2.474)
  rect 0.3x1.3 smd: A1(-3.35,2.474) A4(-2.55,2.474) A5(-1.25,2.474) A6(-0.25,2.474) A7(0.25,2.474) A8(1.25,2.474) A9(2.55,2.474) A12(3.35,2.474) B1(3.05,2.474) B4(2.25,2.474) B5(1.75,2.474) B6(0.75,2.474) B7(-0.75,2.474) B8(-1.75,2.474) B9(-2.25,2.474) B12(-3.05,2.474)
  Board Outline Layer circle w0.005: c-2.9,1.206 r0.375
  Board Outline Layer circle w0.005: c2.9,1.206 r0.375
  Board Outline Layer circle w0.254: c-2.9,1.206 r0.375
  Board Outline Layer circle w0.254: c2.9,1.206 r0.375
  Multi-Layer board cut-out: -2.9,1.581 -3.063,1.543 -3.193,1.439 -3.266,1.289 -3.265,1.122 -3.193,0.972 -3.063,0.868 -2.9,0.831 -2.9,0.831 -2.737,0.868 -2.607,0.972 -2.534,1.122 -2.534,1.289 -2.607,1.439 -2.737,1.544 -2.9,1.581
  Multi-Layer board cut-out: 2.9,1.581 2.737,1.543 2.607,1.439 2.534,1.289 2.534,1.122 2.607,0.972 2.737,0.868 2.9,0.831 2.9,0.831 3.063,0.868 3.193,0.972 3.266,1.122 3.266,1.289 3.193,1.439 3.063,1.544 2.9,1.581
  silkscreen extent -4.47,-5.09 4.47,0.49
VSSOP-8_L2.3-W2.0-P0.50-LS3.1-BR [mm]
  oval 0.905x0.28 smd: 1(1.403,-0.75) 2(1.403,-0.25) 3(1.403,0.25) 4(1.403,0.75) 5(-1.403,0.75) 6(-1.403,0.25) 7(-1.403,-0.25) 8(-1.403,-0.75)
  silkscreen extent -0.72,-1.49 1.55,1.08

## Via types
v1: diameter 24.02, hole 12.01, Top Layer to Bottom Layer, 157 vias

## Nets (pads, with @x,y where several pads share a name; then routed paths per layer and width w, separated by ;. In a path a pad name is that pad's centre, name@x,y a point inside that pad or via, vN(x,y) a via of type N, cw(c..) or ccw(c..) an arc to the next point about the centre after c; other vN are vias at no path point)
3V3_ESP: C43.2 Q16.3 U17.3 U25.5 | length 631
  Top Layer w10: U17.3@3570.16,3631.3 3570.16,3603.07 3576.11,3597.12 C43.2@3576.11,3568.58 3576.11,3492.12 3587.05,3481.18 U25.5@3734.23,3481.18 3759.65,3481.18 3769.65,3491.18 3769.65,3563.58 3789.65,3583.58 3914.65,3583.58 3954.37,3623.31 Q16.3@3954.37,3628.58
5V_FTDI: C24.2 L1.1 USBC2.A4 USBC2.A9 USBC2.B4 USBC2.B9 | length 647.9
  Top Layer w10: C24.2@3516.11,3058.58 L1.1@3583.19,3058.58 3583.19,3162.05 3563.63,3181.61 3563.63,3208.96 3557.19,3215.39 3529.84,3215.39 USBC2.A9@3527.05,3218.18 ; USBC2.B4@3527.05,3230 USBC2.A9@3527.05,3218.18 ; USBC2.B9@3527.05,3407.16 USBC2.A4@3527.05,3418.97 3499.75,3418.97 3487.78,3407 3443.07,3407 3424.65,3388.58 3424.65,3268.58 3463.07,3230.16 3487.78,3230.16 3499.76,3218.18 USBC2.A9@3527.05,3218.18
5V_FTDI_FIL: C25.1 D2.5 L1.2 Q16.1 R13.2 R48.2 U3.20 U24.2 | length 2203
  Top Layer w10: L1.2@3626.11,3058.58 3659.65,3058.58 ; D2.5@3729.41,3323.58 3774.65,3323.58 ; Q16.1@4044.92,3591.18 3977.25,3591.18 3929.65,3543.58 3929.65,3473.58 3899.65,3443.58 3861.69,3443.58 3851.69,3433.58 R48.2@3851.69,3423.58 3851.69,3400.62 3839.65,3388.58 3794.65,3388.58 3774.65,3368.58 3774.65,3323.58 ; U3.20@4081.26,3217.55 4081.26,3173.78 4104.65,3150.39 4104.65,3061.36 4087.58,3044.29 3981.66,3044.29 v1(3974.65,3051.3) 3974.65,3073.92 3764.99,3073.92 3749.65,3058.58 3659.65,3058.58 ; 3659.65,3058.58 3660.16,3059.09 C25.1@3660.16,3143.58 3660.16,3159.09 3684.65,3183.58 3739.65,3183.58 3774.65,3218.58 3774.65,3323.58
  Bottom Layer w10: v1(3974.65,3051.3) 3981.66,3044.29 4580.36,3044.29 4589.65,3053.58 U24.2@4589.65,3093.58
5V_HOST: D1.5 USBC1.A4 USBC1.A9 USBC1.B4 USBC1.B9 | length 722.1
  Top Layer w10: USBC1.B4@3529.8,4283.34 USBC1.A9@3529.8,4271.52 ; USBC1.B9@3529.8,4460.5 USBC1.A4@3529.8,4472.31 3502.49,4472.31 3490.52,4460.35 3461.41,4460.35 3439.65,4438.58 3439.65,4303.58 3459.73,4283.5 3490.52,4283.5 3502.5,4271.52 USBC1.A9@3529.8,4271.52 ; D1.5@3684.41,4353.58 3709.65,4353.58 3719.65,4343.58 3719.65,4288.58 3709.65,4278.58 3684.65,4278.58 3669.65,4263.58 3669.65,4243.58 3644.65,4218.58 3594.65,4218.58 3566.37,4246.86 3566.37,4262.3 3557.15,4271.52 USBC1.A9@3529.8,4271.52
$1N20641: C7.1 U1.73 | length 79.1
  Top Layer w10: C7.1@4116.11,4058.58 4144.65,4058.58 4151.5,4051.73 U1.73@4192.41,4051.73
$1N20642: C4.2 U1.48 | length 74.7
  Top Layer w10: C4.2@4284.65,4617.12 4284.65,4588.58 4292.8,4580.43 U1.48@4292.8,4545.82
$1N20674: U1.80
$1N20676: U1.79
$1N20678: U1.78
$1N21098: R1.2 USBC1.B5 | length 72.9
  Top Layer w10: USBC1.B5@3529.8,4303.02 3565.2,4303.02 3572.61,4295.62 R1.2@3599.65,4295.62
$1N21099: R2.1 USBC1.A5 | length 71.6
  Top Layer w10: USBC1.A5@3529.8,4421.13 3578.38,4421.13 3584.65,4427.4 R2.1@3584.65,4441.54
$2N1585: C20.2 U2.24 | length 68.7
  Top Layer w10: C20.2@5314.65,4332.12 5314.65,4313.58 5319.65,4308.58 5324.65,4308.58 5332.33,4300.9 U2.24@5332.33,4273.7
$2N1590: C23.1 U2.21 | length 100.3
  Top Layer w10: U2.21@5383.12,4273.7 5383.12,4292.05 5389.65,4298.58 5424.65,4298.58 5434.65,4308.58 C23.1@5434.65,4332.12
$2N1592: R8.2 U2.7 | length 62.1
  Top Layer w10: U2.7@5332.33,4163.46 5332.33,4140.9 5354.65,4118.58 R8.2@5354.65,4110.62
$2N1593: R9.2 U2.8 | length 86.4
  Top Layer w10: U2.8@5349.26,4163.46 5349.26,4146.33 5359.5,4136.08 5384.65,4136.08 5394.65,4126.08 R9.2@5394.65,4110.62
$2N1595: R7.1 U2.6 | length 53.2
  Top Layer w10: R7.1@5314.65,4110.62 5314.65,4133.58 5315.4,4134.33 U2.6@5315.4,4163.46
$2N1601: R10.1 U2.13 | length 53.2
  Top Layer w10: U2.13@5433.9,4163.46 5433.9,4139.33 5434.65,4138.58 R10.1@5434.65,4110.62
$2N1605: R6.1 U2.5 | length 66.4
  Top Layer w10: R6.1@5264.65,4160.62 5264.65,4173.58 5284.65,4193.58 5309.3,4193.58 U2.5@5309.69,4193.19
$3N2642: R13.1 R14.1 U3.19 | length 179.6
  Top Layer w10: R13.1@3969.65,3143.24 4014.99,3143.24 4019.65,3138.58 R14.1@4064.31,3138.58 ; U3.19@4055.67,3217.55 4055.67,3147.22 R14.1@4064.31,3138.58 ; R14.1@4064.65,3138.24 R14.1@4064.31,3138.58
$3N2648: U3.23 U4.1 | length 87.3
  Top Layer w10: U3.23@4158.04,3217.55 4158.04,3145.87 U4.1@4169.05,3134.86
$3N2649: U3.22 U5.1 | length 183.4
  Top Layer w10: U3.22@4132.44,3217.55 4132.44,3070.79 4134.65,3068.58 U5.1@4168.17,3068.58
$3N2650: R15.1 U4.2 | length 58.5
  Top Layer w10: U4.2@4232,3134.87 4288.7,3134.87 R15.1@4289.99,3133.58
$3N2651: R16.1 U5.2 | length 58.9
  Top Layer w10: U5.2@4231.12,3068.59 R16.1@4289.99,3068.58
$3N3206: R11.2 USBC2.B5 | length 68
  Top Layer w10: USBC2.B5@3527.05,3249.68 3593.71,3249.68 R11.2@3594.65,3250.62
$3N3207: R12.1 USBC2.A5 | length 78
  Top Layer w10: USBC2.A5@3527.05,3367.79 3578.86,3367.79 3584.65,3373.58 R12.1@3584.65,3391.54
$3N4808: Q17.5 R47.2 | length 105.7
  Top Layer w10: R47.2@4011.69,3898.58 4011.69,3841.54 4034.65,3818.58 Q17.5@4050.86,3818.58
$3N4810: Q17.2 R46.1 | length 98.7
  Top Layer w10: Q17.2@3978.43,3818.58 3999.65,3818.58 4017.61,3800.62 R46.1@4017.61,3748.58
$3N5399: C42.2 U25.4 | length 50
  Top Layer w10: C42.2@3684.65,3555.04 3733.29,3555.04 U25.4@3734.23,3555.98
$3N5472: C28.1 U24.7 | length 677
  Top Layer w10: U24.7@4689.65,3293.58 4704.65,3308.58 4744.65,3308.58 4774.65,3338.58 4774.65,3563.58 4834.65,3623.58 4834.65,3693.58 4909.65,3768.58 C28.1@4997.09,3768.58
$4N17959: CN1.1 U7.2 U7.3 | length 236.6
  Top Layer w10: CN1.1@4835.91,3113.58 4835.91,3184.84 4854.65,3203.58 4914.65,3203.58 4924.65,3213.58 4924.65,3258.36 ; U7.2@4914.81,3258.36 4924.65,3258.36 ; 4924.65,3258.58 4924.65,3258.36 ; U7.3@4934.49,3258.36 4924.65,3258.36
$4N20345: CN7.1 U15.2 U15.3 | length 130.9
  Top Layer w10: U15.3@4569.91,5032.74 U15.2@4589.59,5032.74 ; 4579.65,5033.58 CN7.1@4579.65,5144.84
$4N20830: CN4.1 U12.2 U12.3 | length 302.4
  Top Layer w10: CN4.1@3374.65,4754.84 3473.39,4754.84 3489.65,4738.58 3489.65,4653.58 3504.65,4638.58 3559.43,4638.58 ; U12.3@3559.43,4628.74 3559.43,4638.58 ; U12.2@3559.43,4648.42 3559.43,4638.58
$4N21315: CN3.1 U11.2 U11.3 | length 374.1
  Top Layer w10: CN3.1@3374.65,5124.84 3374.65,5073.58 3399.65,5048.58 3464.65,5048.58 3491.72,5021.51 3491.72,4941.51 3519.65,4913.58 3563.87,4913.58 3564.43,4913.02 ; U11.3@3564.43,4903.74 3564.43,4913.02 ; U11.2@3564.43,4923.42 3564.43,4913.02
$4N21800: CN2.1 U9.2 U9.3 | length 223.7
  Top Layer w10: CN2.1@5200.91,3108.58 5200.91,3189.84 5214.65,3203.58 5254.65,3203.58 5274.65,3223.58 5274.65,3258.36 ; U9.2@5264.81,3258.36 5274.65,3258.36 ; 5274.65,3258.58 5274.65,3258.36 ; U9.3@5284.49,3258.36 5274.65,3258.36
$4N22285: CN6.1 U14.2 U14.3 | length 197.6
  Top Layer w10: CN6.1@5570.91,3113.58 5569.65,3114.84 5569.65,3198.58 5589.65,3218.58 5604.65,3218.58 5614.65,3228.58 5614.65,3263.36 ; U14.2@5604.81,3263.36 5614.65,3263.36 ; 5614.65,3263.58 5614.65,3263.36 ; U14.3@5624.49,3263.36 5614.65,3263.36
$4N22770: CN5.1 U13.2 U13.3 | length 347.6
  Top Layer w10: U13.2@5654,4910.5 U13.3@5654,4930.18 ; 5654.65,4923.58 5679.65,4923.58 5689.65,4933.58 5689.65,5118.58 5709.65,5138.58 5783.39,5138.58 CN5.1@5784.65,5139.84
$6N490: Q15.1 R45.2 ZD1.1 | length 296.7
  Top Layer w23.62: Q15.1@5974.64,3558.78 5974.65,3643.58 5994.65,3663.58 6054.65,3663.58 6072.15,3681.08 6072.15,3713.12 R45.2@6071.69,3713.58 6135.87,3713.58 ZD1.1@6137.25,3714.96
$6N672: P1.1 Q15.2 | length 230.2
  Top Layer w70.87: P1.1@6074.65,3328.58 Q15.2@6074.64,3558.78
+3V3: BOOT.1 C5.1 C6.1 C8.1 C9.1 C10.1 C11.1 C12.1 C13.1 C14.1 C19.1 C21.2 C22.2 C45.1 H2.1 Q1.1 Q2.1 Q3.1 Q4.1 Q5.1 Q6.1 Q7.1 Q8.1 Q9.1 Q10.1 Q11.1 Q12.1 Q13.1 Q14.1 Q16.2 R4.2 R5.2 R6.2 R7.2 R8.1 R9.1 R10.2 R17.2 R18.2 R21.2 R22.2 R25.2 R26.2 R29.2 R30.2 R33.2 R34.2 R37.2 R38.2 R41.2 R42.2 U1.6 U1.11 U1.20 U1.21 U1.27 U1.50 U1.75 U1.100 U2.1 U2.3 U2.22 U2.23 U22.2 U22.4 | length 4058.9
  Top Layer w10: Q8.1@3893.45,4670.33 3894.65,4671.53 3894.65,4688.58 ; Q7.1@3894.02,4526.18 3894.65,4526.81 3894.65,4548.58 ; v1(3894.65,4563.58) 3894.65,4548.58 ; v1(3894.65,4703.58) 3894.65,4688.58 ; v1(3894.65,4843.58) 3894.65,4828.58 ; v1(3894.65,4973.58) 3896.14,4972.08 Q6.1@3896.14,4938.31 ; Q5.1@3896.14,4808.31 3894.65,4809.81 3894.65,4828.58 ; 3899.65,4958.58 3946.69,4958.58 R26.2@3946.78,4958.67 ; R25.2@3946.78,4828.67 3946.69,4828.58 3894.65,4828.58 ; R29.2@3949.65,4546.54 3896.69,4546.54 3894.65,4548.58 ; R30.2@3949.65,4691.54 3897.61,4691.54 3894.65,4688.58 ; Q16.2@4044.92,3665.98 4102.05,3665.98 4124.65,3688.58 H2.1@4184.65,3688.58 ; C5.1@4116.11,4003.58 4154.65,4003.58 ; v1(4154.65,3988.58) 4154.65,4003.58 ; v1(4154.65,4618.58) 4193.19,4618.58 C14.1@4194.65,4617.12 C13.1@4234.65,4617.12 4234.65,4588.58 4253.43,4569.8 U1.50@4253.43,4545.82 ; U1.75@4192.41,4012.36 4191.19,4013.58 4154.65,4013.58 4154.65,4003.58 ; Q13.1@4472.25,4819.21 4509.02,4819.21 v1(4509.65,4818.58) ; R41.2@4492.61,4768.58 4492.61,4816.54 4494.65,4818.58 ; Q14.1@4612.25,4814.21 v1@4644.02,4814.21 ; R42.2@4632.61,4763.58 4632.61,4811.54 v1@4634.65,4813.58 ; U1.27@4706.19,4545.82 4706.19,4585.12 4714.65,4593.58 4759.65,4593.58 ; U1.100@4725.87,3951.34 C6.1@4765.95,3951.34 ; C12.1@4758.19,4618.58 4758.19,4595.04 4759.65,4593.58 ; v1(4760.89,4572.34) 4760.89,4592.34 4759.65,4593.58 ; v1(4764.65,3918.58) 4764.65,3950.04 C6.1@4765.95,3951.34 ; C6.1@4768.19,3953.58 C6.1@4765.95,3951.34 ; U1.20@4786.89,4386.38 4821.85,4386.38 4834.65,4373.58 C11.1@4853.19,4373.58 C10.1@4853.19,4413.58 ; U1.21@4786.89,4406.06 4822.13,4406.06 4829.65,4413.58 C10.1@4853.19,4413.58 ; C8.1@4858.19,4088.58 4844.65,4088.58 4822.45,4110.78 U1.6@4786.89,4110.78 4697.45,4110.78 4674.65,4133.58 v1(4674.65,4178.58) 4674.65,4183.58 4699.65,4208.58 4786.26,4208.58 U1.11@4786.89,4209.21 4830.28,4209.21 4844.65,4223.58 C9.1@4863.19,4223.58 ; v1(4859.65,3468.58) 4874.65,3468.58 ; R18.2@4876.69,3518.58 4876.69,3470.62 4874.65,3468.58 ; v1(4887.67,4453.78) 4879.85,4453.78 4853.19,4427.12 C10.1@4853.19,4413.58 ; Q2.1@4892.05,3462.95 4886.42,3468.58 4874.65,3468.58 ; BOOT.1@4915.67,3643.58 v1(4974.65,3643.58) ; v1(4994.65,3468.58) 5014.65,3468.58 ; R17.2@5013.75,3525.74 5013.75,3469.48 5014.65,3468.58 ; Q1.1@5032.05,3467.95 5031.42,3468.58 5014.65,3468.58 ; v1(5204.65,3463.58) 5219.65,3463.58 ; R22.2@5220.85,3520.2 5220.85,3464.79 5219.65,3463.58 ; R4.2@5224.65,4171.54 5224.65,4133.58 5234.65,4123.58 5261.69,4123.58 R6.2@5264.65,4126.54 5264.65,4093.58 5281.69,4076.54 R7.2@5314.65,4076.54 R8.1@5354.65,4076.54 R9.1@5394.65,4076.54 R10.2@5434.65,4076.54 ; R5.2@5224.65,4280.62 5267.61,4280.62 v1(5274.65,4273.58) ; Q4.1@5241.21,3464.57 5240.23,3463.58 5219.65,3463.58 ; C19.1@5274.65,4317.12 v1(5274.65,4273.58) ; U2.3@5309.69,4227.05 5338.12,4227.05 v1(5354.65,4243.58) 5349.65,4248.58 5349.65,4273.31 U2.23@5349.26,4273.7 5349.26,4303.19 5354.65,4308.58 C22.2@5354.65,4332.12 C21.2@5394.65,4332.12 5394.65,4328.58 5366.19,4300.12 U2.22@5366.19,4273.7 ; U2.1@5315.4,4273.7 5315.28,4273.58 v1(5274.65,4273.58) ; v1(5344.65,3463.58) 5359.65,3463.58 ; R34.2@5355.44,4881.49 5407.55,4881.49 Q10.1@5409.65,4883.58 ; R33.2@5355.44,5011.49 5407.55,5011.49 5409.65,5013.58 ; R21.2@5360.85,3520.2 5360.85,3464.79 5359.65,3463.58 ; Q3.1@5381.21,3464.57 5380.23,3463.58 5359.65,3463.58 ; Q9.1@5409.41,5027.74 5409.65,5027.5 5409.65,5013.58 ; v1(5409.65,4858.58) 5411.07,4860.01 Q10.1@5411.07,4896.85 ; v1(5409.65,4993.58) 5409.65,5013.58 ; v1(5544.65,3473.58) Q12.1@5569.65,3473.58 ; R38.2@5568.86,3529.08 5568.86,3479.37 Q12.1@5569.65,3478.58 ; Q12.1@5582.56,3473.58 Q12.1@5583.3,3474.32 ; v1(5684.65,3473.58) 5699.65,3473.58 ; R37.2@5697.09,3527.4 5699.65,3524.84 5699.65,3473.58 ; Q11.1@5716.78,3474.32 5716.04,3473.58 5699.65,3473.58
  Top Layer w39.37: C45.1@5864.65,4782.19 5908.26,4782.19 v1(5919.65,4793.58) 5929.65,4803.58 v1(5929.65,4828.58) v1(5929.65,4858.58) 5929.65,4898.58 v1(5944.65,4913.58) 5954.65,4923.58 v1(5969.65,4923.58) v1(6004.65,4923.58) v1(6039.65,4923.58) v1(6104.65,4923.58)
  Top Layer w59.06: U22.2@6104.65,4783.63 v1(6104.65,4893.58) v1(6104.65,4923.58) v1(6104.65,4953.58) U22.4@6104.65,5173.54
  other v1: 5229.65,4128.58 4644.65,4813.58 5929.65,4888.58
+5V: C44.1 C46.1 R19.2 R20.2 R23.2 R24.2 R27.2 R28.2 R31.2 R32.2 R35.2 R36.2 R39.2 R40.2 R43.2 R44.2 U7.8 U9.8 U11.8 U12.8 U13.8 U14.8 U15.8 U22.3 U26.2 U26.4 U27.2 | length 477.1
  Top Layer w10: U15.8@4609.28,4922.3 4614.65,4927.67 4614.65,4973.58 4631.69,4990.62 R44.2@4649.65,4990.62 ; R20.2@4849.65,3291.54 4867.61,3291.54 4879.65,3303.58 4879.65,3333.58 4895.12,3349.05 U7.8@4895.12,3368.8 ; R24.2@5199.65,3286.54 5199.81,3286.71 5217.38,3286.71 5224.45,3293.78 5224.45,3318.39 5245.12,3339.05 U9.8@5245.12,3368.8 ; U13.8@5543.56,4890.81 5562.42,4890.81 5580.82,4872.41 R36.2@5580.82,4850.34 ; R40.2@5544.65,3301.54 5557.61,3301.54 5579.65,3323.58 5579.65,3365.78 5585.12,3371.25 U14.8@5585.12,3373.8
+5V_USB_FIL: C39.1 U24.1 U25.1 | length 1062.1
  Top Layer w10: U25.1@3825.07,3481.18 3842.25,3481.18 3863.19,3502.12 3884.65,3502.12 v1(3884.65,3468.58)
  Bottom Layer w10: v1(3884.65,3468.58) 4024.65,3468.58 4349.65,3143.58 4639.65,3143.58 U24.1@4689.65,3093.58
AGND: C26.1 USBC2.0 USBC2.1 USBC2.2 USBC2.3 | length 770.1
  Top Layer w10: USBC2.2@3332.24,3148.3 3332.24,3095.99 3358.19,3070.04 C26.1@3358.19,3058.58
  Top Layer w39.37: USBC2.1@3496.8,3148.3 USBC2.2@3332.24,3148.3 USBC2.3@3332.24,3488.86 USBC2.0@3496.8,3488.86
AGND1: C2.1 USBC1.0 USBC1.1 USBC1.2 USBC1.3 | length 710.3
  Top Layer w10: C2.1@3393.19,4583.58 3394.65,4582.12 3394.65,4543.58 ; USBC1.1@3499.55,4201.64 USBC1.2@3334.99,4201.64 USBC1.3@3334.99,4542.2 USBC1.0@3499.55,4542.2
BOOT: BOOT.2 C3.2 R3.2 U1.94 | length 454.1
  Top Layer w10: R3.2@4554.65,3880.62 4555.23,3880.04 C3.2@4604.65,3880.04 ; U1.94@4607.76,3951.34 4607.76,3906.69 4604.65,3903.58 C3.2@4604.65,3880.04 ; BOOT.2@4743.63,3643.58 4743.63,3754.6 4724.65,3773.58 4679.65,3773.58 4644.65,3808.58 4644.65,3858.58 4623.19,3880.04 C3.2@4604.65,3880.04
C_DN: D1.4 USBC1.A7 USBC1.B7 | length 245.4
  Top Layer w10: USBC1.A7@3529.8,4362.08 3565.39,4362.08 3567.23,4360.24 ; USBC1.B7@3529.8,4401.45 3561.78,4401.45 3567.23,4396 3567.23,4360.24 ; D1.4@3684.41,4390.98 3674.7,4390.98 3652.32,4368.6 3652.32,4365.52 3647.04,4360.24 3567.23,4360.24
C_DP: D1.6 USBC1.A6 USBC1.B6 | length 280.1
  Top Layer w10: USBC1.A6@3529.8,4381.76 3497.83,4381.76 3489.65,4373.58 3489.65,4348.58 3495.84,4342.39 USBC1.B6@3529.8,4342.39 3565.39,4342.39 3567.23,4344.24 3649.72,4344.24 3652.32,4341.64 3652.32,4338.56 3674.7,4316.18 D1.6@3684.41,4316.18
DTR: U3.2 U24.8 | length 493.5
  Top Layer w10: U3.2@4260.4,3489.61 4260.4,3382.83 4289.65,3353.58 4349.65,3353.58 4359.65,3343.58 4574.65,3343.58 4589.65,3328.58 U24.8@4589.65,3293.58
DTR1: Q17.1 R47.1 U24.9 | length 1059.8
  Top Layer w10: R47.1@3977.61,3898.58 3977.61,3845 Q17.1@3978.43,3844.17
  Bottom Layer w10: v1(3974.65,3868.58) 4054.65,3868.58 4084.65,3838.58 4084.65,3648.58 4119.65,3613.58 4354.65,3613.58 4409.65,3558.58 4409.65,3318.58 4434.65,3293.58 U24.9@4489.65,3293.58
DUP4: U1.84 U7.1 U7.7 | length 1375.8
  Top Layer w10: v1(4409.65,3883.58) 4409.65,3903.58 4410.91,3904.84 U1.84@4410.91,3951.34 ; U7.1@4895.12,3258.36 4894.65,3258.83 4894.65,3303.58 v1(4904.65,3313.58) 4914.81,3323.74 U7.7@4914.81,3368.8
  Bottom Layer w10: v1(4409.65,3883.58) 4409.65,3858.58 4416.72,3851.51 4501.72,3851.51 4674.65,3678.58 4999.65,3678.58 5039.65,3638.58 5039.65,3343.58 5009.65,3313.58 v1(4904.65,3313.58)
DUP5: U1.57 U11.1 U11.7 | length 1065.5
  Top Layer w10: U11.1@3564.43,4943.11 3600.12,4943.11 3619.81,4923.42 U11.7@3674.87,4923.42 ; v1(4129.65,4378.58) 4144.65,4378.58 4156.54,4366.69 U1.57@4192.41,4366.69
  Bottom Layer w10: v1(3619.65,4923.58) 3619.65,4678.58 3919.65,4378.58 v1(4129.65,4378.58)
DUP6: U13.1 U13.7 | length 118.6
  Top Layer w10: U13.7@5543.56,4910.5 5582.73,4910.5 5602.42,4890.81 U13.1@5654,4890.81
DUP7: U15.1 U15.7 | length 118.6
  Top Layer w10: U15.7@4589.59,4922.3 4589.59,4978.53 4609.28,4998.22 U15.1@4609.28,5032.74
